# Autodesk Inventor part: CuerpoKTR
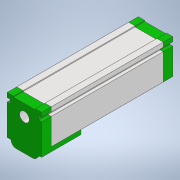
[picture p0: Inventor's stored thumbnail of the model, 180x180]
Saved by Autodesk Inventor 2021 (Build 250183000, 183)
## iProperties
Created: 2021-02
Part Number: CuerpoKTR
Material: Genérico
Document SubType Name: Modeling
Designer: ATOUZA
Density: 1 g/cm^3
Appearance: Valor por defecto
Author: ATOUZA
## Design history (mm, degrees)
sketch "Boceto2"
  geometry: L1 (9, -9)-(-9, -9); L2 (-9, 9)-(9, -9); L3 (9, 9)-(-9, -9); L4 (9, 6.7)-(7.4, 6.7); L5 (7.4, 6.7)-(7.4, 4.7); L6 (7.4, 4.7)-(9, 4.7); L7 (5.7, 9)-(5.7, 8.5); L8 (5.7, 8.5)-(-5.7, 8.5); L9 (-5.7, 8.5)-(-5.7, 9); L10 (0, 9)-(0, 0); L11 (-9, 9)-(-5.7, 9); L12 (5.7, 9)-(9, 9); L13 (9, 9)-(9, 6.7); L14 (9, 4.7)-(9, -9); L15 (-7.4, 4.7)-(-9, 4.7); L16 (-7.4, 6.7)-(-7.4, 4.7); L17 (-9, 6.7)-(-7.4, 6.7); L18 (-9, -9)-(-9, 4.7); L19 (-9, 6.7)-(-9, 9); 2 further points
  constraints: 38 end point, 10 perpendicular, 6 parallel, 5 midpoint, 4 symmetric about line, 3 horizontal, 1 point on line
  dimensions: "d0" = 18 distance of L1.start L1.end; "d1" = 18 distance of L3.start L1.start; "d3" = 2 distance between parallel lines of L6 L4; "d5" = 11.4 distance between parallel lines of L7 L9; "d7" = 1.6 distance between parallel lines of L13 L5; "d8" = 2.3 distance between parallel lines of L12 L4; "d9" = 0.5 distance between parallel lines of L11 L8
extrude "Extrusión1" new body sketch "Boceto2" distance "d10" = 58.4; taper "d11" = 0 deg
sketch "Boceto3"
  geometry: L1 (9, 6.7)-(7.4, 6.7) reference; L2 (9, 9)-(9, 6.7) reference; L3 (5.7, 9)-(9, 9) reference; L4 (5.7, 8.5)-(5.7, 9) reference; L5 (-5.7, 8.5)-(5.7, 8.5) reference; L6 (-5.7, 9)-(-5.7, 8.5) reference; L7 (-9, 9)-(-5.7, 9) reference; L8 (-9, 6.7)-(-9, 9) reference; L9 (-7.4, 6.7)-(-9, 6.7) reference; L10 (-7.4, 4.7)-(-7.4, 6.7) reference; L11 (-9, 4.7)-(-7.4, 4.7) reference; L12 (-9, -9)-(-9, 4.7) reference; L13 (9, -9)-(-9, -9) reference; L14 (9, 4.7)-(9, -9) reference; L15 (7.4, 4.7)-(9, 4.7) reference; L16 (7.4, 6.7)-(7.4, 4.7) reference; 1 further point
extrude "Extrusión2" new body sketch "Boceto3" distance "d12" = 5; taper "d13" = 0 deg
sketch "Boceto4"
  geometry: L1 (-9, 6.7)-(-7.4, 6.7) reference; L2 (-7.4, 6.7)-(-7.4, 4.7) reference; L3 (-7.4, 4.7)-(-9, 4.7) reference; L4 (-9, 4.7)-(-9, -9) reference; L5 (-9, -9)-(9, -9) reference; L6 (9, -9)-(9, 4.7) reference; L7 (9, 4.7)-(7.4, 4.7) reference; L8 (7.4, 4.7)-(7.4, 6.7) reference; L9 (7.4, 6.7)-(9, 6.7) reference; L10 (9, 6.7)-(9, 9) reference; L11 (9, 9)-(5.7, 9) reference; L12 (5.7, 9)-(5.7, 8.5) reference; L13 (5.7, 8.5)-(-5.7, 8.5) reference; L14 (-5.7, 8.5)-(-5.7, 9) reference; L15 (-5.7, 9)-(-9, 9) reference; L16 (-9, 9)-(-9, 6.7) reference; 1 further point
extrude "Extrusión3" new body sketch "Boceto4" distance "d14" = 5; taper "d15" = 0 deg
sketch "Boceto5"
  geometry: L1 (9, -9)-(-9, -9) reference; L2 (-9, -9)-(9, -9); L3 (9, -9)-(9, -11.3); L4 (-9, -11.3)-(-9, -9); L5 (4.3, -14)-(-4.3, -14); L6 (-3.479, -9.115)-(4.3, -14); L7 (3.479, -9.115)-(-4.3, -14); L8 (9, -11.3)-(7, -11.3); L9 (-7, -11.3)-(-9, -11.3); A1 r 2.7 centre (-4.3, -11.3) between (-7, -11.3) and (-4.3, -14); A2 r 2.7 centre (4.3, -11.3) between (4.3, -14) and (7, -11.3); 2 further points
  constraints: 16 end point, 4 point on circle, 3 parallel, 2 centre point, 1 horizontal, 1 perpendicular
  dimensions: "d16" = 2.3 distance of L2.end L3.end; "d18" = 5 distance between parallel lines of L1 L5; "d19" = 8.6 distance of L5.start L5.end; "d20" = 2.7 radius of A2; "d21" = 2.7 radius of A1; "d22" = 2.3 distance between parallel lines of L1 L9; "d23" = 2.3 distance from line of L1 A2.centre; "d24" = 2.3 distance from line of L1 A1.centre; "d25" = 4.7 horizontal distance of L4.start L5.end
extrude "Extrusión4" join sketch "Boceto5" distance "d26" = 20.5; taper "d27" = 0 deg
sketch "Boceto6"
  geometry: L1 (5.7, 8.5)-(-5.7, 8.5) reference; L2 (-9, -11.3)-(-7, -11.3) reference; C1 r 2.5 at (0, 2.5); 1 further point
  constraints: 1 centre point
  dimensions: "d28" = 5 diameter of C1; "d29" = 6 distance from line of L1 C1.centre
extrude "Extrusión5" cut sketch "Boceto6" extent not by distance; stored distance "d31" = 76.9; taper "d32" = 0 deg
node "Sólido1"
node "Contorno proyectado1"
node "Sólido2"
node "Contorno proyectado2"
node "Sólido3"
other parameters: "d2" = 2.3, "d4" = 1.6, "d6" = 0.5
